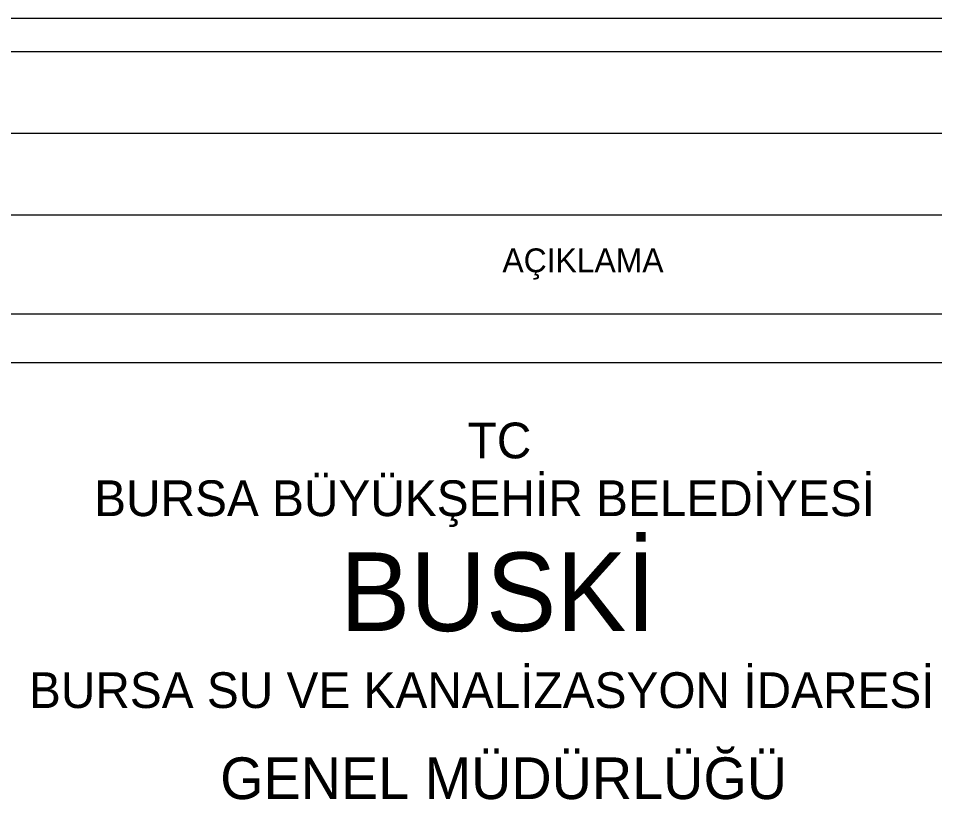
# Model space of a CAD drawing. Extents: x -17 to 1145, y -10 to 821.
# Drawn here: x 1005.2 to 1082.1, y 221.4 to 287 of the extents above; entities that cross this region are included whole.
import ezdxf

# ---------------------------------------------------------------- set-up
doc = ezdxf.new("R2010")
doc.units = 0
for name, color, linetype in [('Level 1', 7, 'Continuous'), ('Level 20', 7, 'Continuous'), ('Level 6', 7, 'Continuous'), ('Level 7', 7, 'Continuous')]:
    doc.layers.add(name, color=color, linetype=linetype)

msp = doc.modelspace()

# ---------------------------------------------------------------- linework, layer by layer
at = {"layer": 'Level 1'}
msp.add_line((960, 287), (1135, 287), dxfattribs=at)
at = {"layer": 'Level 6'}
for p, q in [((963.472, 284.215), (1131.447, 284.215)), ((963.472, 284.215), (1131.447, 284.215)), ((963.472, 284.215), (1131.447, 284.215)), ((963.472, 284.215), (1131.447, 284.215)), ((966.601, 284.215), (1128.318, 284.215)), ((966.601, 284.215), (1128.318, 284.215)), ((966.601, 284.215), (1128.318, 284.215)), ((966.601, 284.215), (1128.318, 284.215)), ((966.601, 284.215), (1128.318, 284.215)), ((966.601, 284.215), (1128.318, 284.215)), ((966.601, 284.215), (1128.318, 284.215)), ((966.601, 284.215), (1128.318, 284.215)), ((963.472, 277.351), (1131.447, 277.351)), ((963.472, 277.351), (1131.447, 277.351)), ((963.472, 277.351), (1131.447, 277.351)), ((963.472, 277.351), (1131.447, 277.351)), ((963.472, 270.492), (1131.447, 270.492)), ((963.472, 270.492), (1131.447, 270.492)), ((963.472, 270.492), (1131.447, 270.492)), ((963.472, 270.492), (1131.447, 270.492)), ((963.472, 262.2), (1131.447, 262.2)), ((963.472, 262.2), (1131.447, 262.2)), ((963.472, 262.2), (1131.447, 262.2)), ((963.472, 262.2), (1131.447, 262.2)), ((963.472, 258.106), (1131.447, 258.106)), ((963.472, 258.106), (1131.447, 258.106)), ((963.472, 258.106), (1131.447, 258.106)), ((963.472, 258.106), (1131.447, 258.106))]:
    msp.add_line(p, q, dxfattribs=at)

# ---------------------------------------------------------------- texts
at = {"layer": 'Level 20'}
msp.add_text('GENEL MÜDÜRLÜĞÜ', height=3.5, dxfattribs=at).set_placement((1022.138, 221.454))
at = {"layer": 'Level 7'}
for s, height, p in [('AÇIKLAMA', 2, (1045.832, 265.683)), ('TC', 3, (1042.911, 250.06)), ('BURSA BÜYÜKŞEHİR BELEDİYESİ', 3, (1011.56, 245.211)), ('BUSKİ', 6.6017, (1032.197, 235.558)), ('BURSA SU VE KANALİZASYON İDARESİ', 3, (1006.085, 229.1))]:
    msp.add_text(s, height=height, dxfattribs=at).set_placement(p)

doc.saveas('drawing.dxf')
